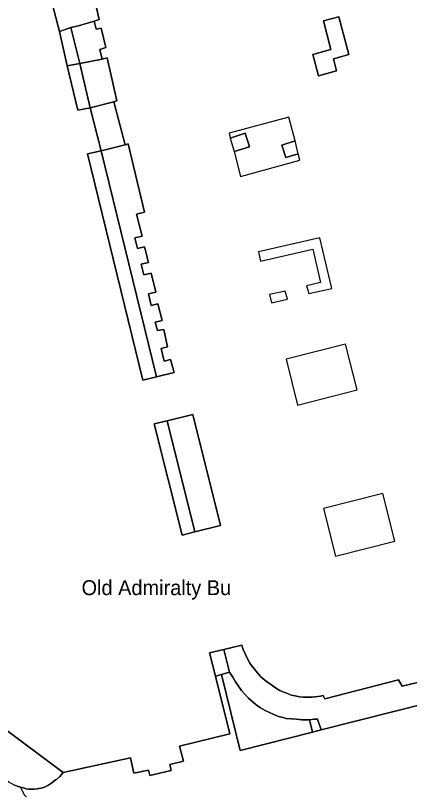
# Model space of a CAD drawing. Extents: x 529240 to 530363, y 179600 to 180767.
# Drawn here: x 529918.6 to 529964.9, y 180142.8 to 180233.6 of the extents above; entities that cross this region are included whole.
import ezdxf

# ---------------------------------------------------------------- set-up
doc = ezdxf.new("R2010")
doc.units = 0
for name, color, linetype in [('Building', 7, 'Continuous'), ('General surface', 7, 'Continuous'), ('Roadside', 7, 'Continuous'), ('Unclassified', 7, 'Continuous')]:
    doc.layers.add(name, color=color, linetype=linetype)

msp = doc.modelspace()

# ---------------------------------------------------------------- linework, layer by layer
at = {"layer": 'Building'}
for points in [[(529935.45, 180242.8), (529934.3, 180242.55), (529934.4, 180242.05), (529933.3, 180241.75), (529933.5, 180241.05), (529931.55, 180240.6), (529931.4, 180241.25), (529930, 180240.9), (529930.15, 180240.2), (529928.15, 180239.7), (529928.05, 180240.35), (529926.8, 180240.05), (529926.95, 180239.4), (529926.3, 180239.25), (529926.6, 180238.1), (529927.25, 180238.25), (529927.65, 180236.45), (529927, 180236.35), (529927.25, 180235.2), (529927.95, 180235.35), (529928.45, 180233.1), (529927.9, 180232.9)], [(529927.95, 180235.35), (529928.45, 180233.1), (529927.9, 180232.9), (529928.1, 180231.95), (529928.7, 180232.1), (529929.25, 180229.8), (529928.55, 180229.6), (529928.8, 180228.45), (529929.4, 180228.6), (529930.55, 180223.55), (529930.2, 180223.45), (529931.5, 180218.4), (529931.85, 180218.5), (529933.8, 180210.5), (529932.85, 180210.25), (529933.5, 180207.7), (529932.65, 180207.5), (529932.95, 180206.25), (529933.8, 180206.45), (529934.25, 180204.6), (529933.4, 180204.4), (529933.7, 180203.15), (529934.55, 180203.35), (529935.1, 180201.1), (529934.25, 180200.9), (529934.55, 180199.55), (529935.35, 180199.75), (529935.85, 180197.8), (529935.05, 180197.6), (529935.3, 180196.6), (529936.05, 180196.75), (529936.5, 180194.7), (529935.75, 180194.5), (529936.1, 180193), (529936.85, 180193.2), (529937.25, 180191.7), (529935.2, 180191.2), (529933.6, 180190.8), (529927.1, 180217.35), (529928.7, 180217.7), (529927.4, 180222.75), (529925.95, 180222.45), (529924.7, 180227.65), (529923.8, 180231.7), (529922.15, 180238.15)], [(529923.8, 180231.7), (529922.15, 180238.15)], [(529927.9, 180232.9), (529926.05, 180232.35)], [(529928.8, 180228.45), (529928.55, 180229.6), (529929.25, 180229.8), (529928.7, 180232.1), (529928.1, 180231.95), (529927.9, 180232.9)], [(529954.2, 180226.5), (529953.55, 180229), (529955.65, 180229.6), (529954.8, 180232.95), (529956.6, 180233.4), (529957.75, 180229), (529955.95, 180228.5), (529956.3, 180227.1), (529954.2, 180226.5)], [(529925.15, 180232.15), (529923.8, 180231.7)], [(529926.05, 180232.35), (529925.15, 180232.15)], [(529925.15, 180232.15), (529926.2, 180227.95)], [(529923.8, 180231.7), (529924.7, 180227.65)], [(529926.2, 180227.95), (529928.8, 180228.45)], [(529930.2, 180223.45), (529930.55, 180223.55), (529929.4, 180228.6), (529928.8, 180228.45)], [(529924.7, 180227.65), (529926.2, 180227.95)], [(529924.7, 180227.65), (529925.95, 180222.45), (529927.4, 180222.75)], [(529927.4, 180222.75), (529930.2, 180223.45)], [(529927.4, 180222.75), (529928.7, 180217.7)], [(529930.2, 180223.45), (529931.5, 180218.4)], [(529951.45, 180218.85), (529950.7, 180221.65), (529943.7, 180219.75)], [(529943.7, 180219.75), (529943.85, 180219.2)], [(529943.85, 180219.2), (529944.3, 180217.6)], [(529928.7, 180217.7), (529931.5, 180218.4)], [(529931.5, 180218.4), (529931.85, 180218.5), (529933.8, 180210.5), (529932.85, 180210.25), (529933.5, 180207.7), (529932.65, 180207.5), (529932.95, 180206.25), (529933.8, 180206.45), (529934.25, 180204.6), (529933.4, 180204.4), (529933.7, 180203.15), (529934.55, 180203.35), (529935.1, 180201.1), (529934.25, 180200.9), (529934.55, 180199.55), (529935.35, 180199.75), (529935.85, 180197.8), (529935.05, 180197.6), (529935.3, 180196.6), (529936.05, 180196.75), (529936.5, 180194.7), (529935.75, 180194.5), (529936.1, 180193), (529936.85, 180193.2), (529937.25, 180191.7), (529935.2, 180191.2)], [(529951.8, 180217.35), (529951.45, 180218.85)], [(529888.1, 180217.5), (529902.05, 180161.3), (529924.25, 180144.75)], [(529935.2, 180191.2), (529933.6, 180190.8), (529927.1, 180217.35), (529928.7, 180217.7)], [(529944.3, 180217.6), (529945.05, 180214.7), (529952, 180216.6), (529951.8, 180217.35)], [(529955.75, 180201.55), (529954.35, 180207.5), (529947.15, 180205.85), (529947.4, 180204.75), (529953.55, 180206.15), (529954.45, 180202.25), (529952.8, 180201.85), (529953.05, 180200.95), (529955.75, 180201.55)], [(529950.55, 180200.3), (529950.3, 180201.25), (529948.45, 180200.85), (529948.7, 180199.85), (529950.55, 180200.3)], [(529958.75, 180189.65), (529957.35, 180195), (529950.4, 180193.25), (529951.75, 180187.85), (529958.75, 180189.65)], [(529936.45, 180186), (529939.45, 180186.75), (529942.7, 180173.75), (529939.7, 180173)], [(529939.7, 180173), (529938.2, 180172.6), (529934.9, 180185.65), (529936.45, 180186)], [(529963.15, 180171.9), (529961.75, 180177.5), (529954.8, 180175.75), (529956.2, 180170.15), (529963.15, 180171.9)], [(529902.05, 180161.3), (529924.25, 180144.75), (529932.15, 180146.5), (529932.55, 180144.7), (529934.25, 180145.05), (529934.4, 180144.4), (529936.9, 180145), (529936.75, 180145.7), (529938.35, 180146.1), (529937.9, 180147.85), (529943.8, 180149.3), (529942.1, 180156.05), (529941.4, 180158.8), (529943.1, 180159.2), (529945.2, 180159.7), (529945.35, 180159.2), (529945.85, 180158.1), (529946.15, 180157.6), (529946.35, 180157.3), (529946.7, 180156.9), (529947.05, 180156.45), (529947.45, 180156), (529947.9, 180155.6), (529948.2, 180155.35), (529948.7, 180155.05), (529949.15, 180154.7), (529949.65, 180154.4), (529950.2, 180154.15), (529950.5, 180154.05), (529951, 180153.85), (529951.45, 180153.75), (529951.95, 180153.65), (529952.45, 180153.6), (529953.45, 180153.6), (529954.45, 180153.7), (529954.75, 180153.8), (529954.95, 180153.4), (529963.6, 180155.65), (529964, 180154.9), (529966.8, 180155.55)], [(529942.1, 180156.05), (529941.4, 180158.8), (529943.1, 180159.2)], [(529943.1, 180159.2), (529945.2, 180159.7), (529945.35, 180159.2), (529945.85, 180158.1), (529946.15, 180157.6), (529946.35, 180157.3), (529946.7, 180156.9), (529947.05, 180156.45), (529947.45, 180156), (529947.9, 180155.6), (529948.2, 180155.35), (529948.7, 180155.05), (529949.15, 180154.7), (529949.65, 180154.4), (529950.2, 180154.15), (529950.5, 180154.05), (529951, 180153.85), (529951.45, 180153.75), (529951.95, 180153.65), (529952.45, 180153.6), (529953.45, 180153.6), (529954.45, 180153.7), (529954.75, 180153.8), (529954.95, 180153.4), (529963.6, 180155.65), (529964, 180154.9), (529966.8, 180155.55)], [(529924.25, 180144.75), (529932.15, 180146.5), (529932.55, 180144.7), (529934.25, 180145.05), (529934.4, 180144.4), (529936.9, 180145), (529936.75, 180145.7), (529938.35, 180146.1), (529937.9, 180147.85), (529943.8, 180149.3), (529942.1, 180156.05)]]:
    msp.add_lwpolyline(points, dxfattribs=at)
for points in [[(529926.2, 180227.95), (529928.8, 180228.45), (529928.55, 180229.6), (529929.25, 180229.8), (529928.7, 180232.1), (529928.1, 180231.95), (529927.9, 180232.9), (529926.05, 180232.35), (529925.15, 180232.15)], [(529954.2, 180226.5), (529956.3, 180227.1), (529955.95, 180228.5), (529957.75, 180229), (529956.6, 180233.4), (529954.8, 180232.95), (529955.65, 180229.6), (529953.55, 180229)], [(529925.15, 180232.15), (529923.8, 180231.7), (529924.7, 180227.65), (529926.2, 180227.95)], [(529927.4, 180222.75), (529928.7, 180217.7), (529931.5, 180218.4), (529930.2, 180223.45)], [(529951.8, 180217.35), (529951.45, 180218.85), (529950.7, 180221.65), (529943.7, 180219.75), (529943.85, 180219.2), (529944.3, 180217.6), (529945.05, 180214.7), (529952, 180216.6)], [(529944.3, 180217.6), (529946.1, 180218.15), (529945.6, 180219.75), (529943.85, 180219.2)], [(529951.45, 180218.85), (529949.9, 180218.35), (529950.35, 180216.9), (529951.8, 180217.35)], [(529953.05, 180200.95), (529955.75, 180201.55), (529954.35, 180207.5), (529947.15, 180205.85), (529947.4, 180204.75), (529953.55, 180206.15), (529954.45, 180202.25), (529952.8, 180201.85)], [(529948.7, 180199.85), (529950.55, 180200.3), (529950.3, 180201.25), (529948.45, 180200.85)], [(529951.75, 180187.85), (529958.75, 180189.65), (529957.35, 180195), (529950.4, 180193.25)], [(529938.2, 180172.6), (529939.7, 180173), (529942.7, 180173.75), (529939.45, 180186.75), (529936.45, 180186), (529934.9, 180185.65)], [(529956.2, 180170.15), (529963.15, 180171.9), (529961.75, 180177.5), (529954.8, 180175.75)]]:
    msp.add_lwpolyline(points, close=True, dxfattribs=at)
at = {"layer": 'General surface'}
for points in [[(529922.15, 180238.15), (529923.8, 180231.7), (529925.15, 180232.15), (529926.05, 180232.35), (529927.9, 180232.9), (529928.45, 180233.1), (529927.95, 180235.35)], [(529918.45, 180143.3), (529918.85, 180143.15), (529919.25, 180143.03), (529919.6, 180142.95), (529919.9, 180142.85), (529920.2, 180142.8), (529920.85, 180142.8), (529921.2, 180142.85), (529921.8, 180142.95), (529922.05, 180143.05), (529922.45, 180143.25), (529922.9, 180143.55), (529923.35, 180143.9), (529923.45, 180143.95), (529923.85, 180144.3), (529924.25, 180144.75), (529902.05, 180161.3)], [(529966.8, 180155.55), (529964, 180154.9), (529963.6, 180155.65), (529954.95, 180153.4), (529954.75, 180153.8), (529954.45, 180153.7), (529953.45, 180153.6), (529952.45, 180153.6), (529951.95, 180153.65), (529951.45, 180153.75), (529951, 180153.85), (529950.5, 180154.05), (529950.2, 180154.15), (529949.65, 180154.4), (529949.15, 180154.7), (529948.7, 180155.05), (529948.2, 180155.35), (529947.9, 180155.6), (529947.45, 180156), (529947.05, 180156.45), (529946.7, 180156.9), (529946.35, 180157.3), (529946.15, 180157.6), (529945.85, 180158.1), (529945.35, 180159.2), (529945.2, 180159.7), (529943.1, 180159.2), (529943.75, 180156.55), (529944.15, 180155.95), (529944.45, 180155.4), (529945.15, 180154.4), (529945.55, 180153.95), (529946, 180153.5), (529946.9, 180152.7), (529947.4, 180152.35), (529947.95, 180152.05), (529948.95, 180151.55), (529949.5, 180151.35), (529950.05, 180151.2), (529950.4, 180151.1), (529951.05, 180151.05), (529951.6, 180151), (529952.25, 180150.95), (529953.15, 180150.95), (529953.65, 180151), (529954.1, 180151), (529954.5, 180149.75), (529980.1, 180156.2)], [(529980.1, 180156.2), (529954.5, 180149.75), (529953.5, 180149.5), (529945, 180147.35), (529942.8, 180156.25), (529942.1, 180156.05), (529943.8, 180149.3), (529937.9, 180147.85), (529938.35, 180146.1), (529936.75, 180145.7), (529936.9, 180145), (529934.4, 180144.4), (529934.25, 180145.05), (529932.55, 180144.7), (529932.15, 180146.5), (529924.25, 180144.75), (529923.85, 180144.3), (529923.45, 180143.95), (529923.35, 180143.9), (529922.9, 180143.55), (529922.45, 180143.25), (529922.05, 180143.05), (529921.8, 180142.95), (529921.2, 180142.85), (529920.85, 180142.8), (529920.2, 180142.8), (529919.9, 180142.85), (529919.6, 180142.95), (529919.25, 180143.03), (529919.7, 180142.1)]]:
    msp.add_lwpolyline(points, dxfattribs=at)
for points in [[(529954.2, 180226.5), (529956.3, 180227.1), (529955.95, 180228.5), (529957.75, 180229), (529956.6, 180233.4), (529954.8, 180232.95), (529955.65, 180229.6), (529953.55, 180229)], [(529930.2, 180223.45), (529930.55, 180223.55), (529929.4, 180228.6), (529928.8, 180228.45), (529926.2, 180227.95), (529927.4, 180222.75)], [(529927.4, 180222.75), (529926.2, 180227.95), (529924.7, 180227.65), (529925.95, 180222.45)], [(529943.85, 180219.2), (529945.6, 180219.75), (529946.1, 180218.15), (529944.3, 180217.6), (529945.05, 180214.7), (529952, 180216.6), (529951.8, 180217.35), (529950.35, 180216.9), (529949.9, 180218.35), (529951.45, 180218.85), (529950.7, 180221.65), (529943.7, 180219.75)], [(529931.5, 180218.4), (529928.7, 180217.7), (529935.2, 180191.2), (529937.25, 180191.7), (529936.85, 180193.2), (529936.1, 180193), (529935.75, 180194.5), (529936.5, 180194.7), (529936.05, 180196.75), (529935.3, 180196.6), (529935.05, 180197.6), (529935.85, 180197.8), (529935.35, 180199.75), (529934.55, 180199.55), (529934.25, 180200.9), (529935.1, 180201.1), (529934.55, 180203.35), (529933.7, 180203.15), (529933.4, 180204.4), (529934.25, 180204.6), (529933.8, 180206.45), (529932.95, 180206.25), (529932.65, 180207.5), (529933.5, 180207.7), (529932.85, 180210.25), (529933.8, 180210.5), (529931.85, 180218.5)], [(529935.2, 180191.2), (529928.7, 180217.7), (529927.1, 180217.35), (529933.6, 180190.8)], [(529955.75, 180201.55), (529954.35, 180207.5), (529947.15, 180205.85), (529947.4, 180204.75), (529953.55, 180206.15), (529954.45, 180202.25), (529952.8, 180201.85), (529953.05, 180200.95)], [(529950.55, 180200.3), (529950.3, 180201.25), (529948.45, 180200.85), (529948.7, 180199.85)], [(529958.75, 180189.65), (529957.35, 180195), (529950.4, 180193.25), (529951.75, 180187.85)], [(529936.45, 180186), (529939.7, 180173), (529942.7, 180173.75), (529939.45, 180186.75)], [(529939.7, 180173), (529936.45, 180186), (529934.9, 180185.65), (529938.2, 180172.6)], [(529963.15, 180171.9), (529961.75, 180177.5), (529954.8, 180175.75), (529956.2, 180170.15)], [(529942.8, 180156.25), (529943.75, 180156.55), (529943.1, 180159.2), (529941.4, 180158.8), (529942.1, 180156.05)], [(529953.15, 180150.95), (529952.25, 180150.95), (529951.6, 180151), (529951.05, 180151.05), (529950.4, 180151.1), (529950.05, 180151.2), (529949.5, 180151.35), (529948.95, 180151.55), (529947.95, 180152.05), (529947.4, 180152.35), (529946.9, 180152.7), (529946, 180153.5), (529945.55, 180153.95), (529945.15, 180154.4), (529944.45, 180155.4), (529944.15, 180155.95), (529943.75, 180156.55), (529942.8, 180156.25), (529945, 180147.35), (529953.5, 180149.5)], [(529953.5, 180149.5), (529954.5, 180149.75), (529954.1, 180151), (529953.65, 180151), (529953.15, 180150.95)]]:
    msp.add_lwpolyline(points, close=True, dxfattribs=at)
at = {"layer": 'Roadside'}
msp.add_lwpolyline([(529919.7, 180142.1), (529919.25, 180143.03), (529918.85, 180143.15), (529918.45, 180143.3)], dxfattribs=at)
at = {"layer": 'Unclassified'}
for points in [[(529926.2, 180227.95), (529927.4, 180222.75)], [(529943.85, 180219.2), (529945.6, 180219.75), (529946.1, 180218.15), (529944.3, 180217.6)], [(529951.45, 180218.85), (529949.9, 180218.35), (529950.35, 180216.9), (529951.8, 180217.35)], [(529928.7, 180217.7), (529935.2, 180191.2)], [(529936.45, 180186), (529939.7, 180173)], [(529943.75, 180156.55), (529943.1, 180159.2)], [(529919.25, 180143.03), (529918.85, 180143.15), (529918.45, 180143.3), (529918.1, 180143.5), (529917.9, 180143.6), (529903.3, 180155.55), (529902.4, 180156.45), (529902.05, 180156.85), (529901.7, 180157.3), (529901.25, 180158.05)], [(529942.8, 180156.25), (529943.75, 180156.55)], [(529943.75, 180156.55), (529944.15, 180155.95), (529944.45, 180155.4), (529945.15, 180154.4), (529945.55, 180153.95), (529946, 180153.5), (529946.9, 180152.7), (529947.4, 180152.35), (529947.95, 180152.05), (529948.95, 180151.55), (529949.5, 180151.35), (529950.05, 180151.2), (529950.4, 180151.1), (529951.05, 180151.05), (529951.6, 180151), (529952.25, 180150.95), (529953.15, 180150.95)], [(529942.1, 180156.05), (529942.8, 180156.25)], [(529942.8, 180156.25), (529945, 180147.35), (529953.5, 180149.5)], [(529954.5, 180149.75), (529980.1, 180156.2)], [(529953.15, 180150.95), (529953.65, 180151), (529954.1, 180151), (529954.5, 180149.75)], [(529953.15, 180150.95), (529953.5, 180149.5)], [(529953.5, 180149.5), (529954.5, 180149.75)], [(529924.25, 180144.75), (529923.85, 180144.3), (529923.45, 180143.95), (529923.35, 180143.9), (529922.9, 180143.55), (529922.45, 180143.25), (529922.05, 180143.05), (529921.8, 180142.95), (529921.2, 180142.85), (529920.85, 180142.8), (529920.2, 180142.8), (529919.9, 180142.85), (529919.6, 180142.95), (529919.25, 180143.03)], [(529919.25, 180143.03), (529919.7, 180142.1), (529920.9, 180141), (529921.9, 180140), (529922.8, 180138.6), (529923.2, 180137.95), (529923.6, 180137.2), (529923.8, 180136.9), (529924.55, 180135.35), (529925.2, 180134.1), (529926.85, 180130.35), (529927.5, 180128.55), (529927.95, 180127.25), (529928.5, 180125.1), (529931.174, 180114)]]:
    msp.add_lwpolyline(points, dxfattribs=at)

# ---------------------------------------------------------------- texts
msp.add_text('Old Admiralty Bu', height=1.75, dxfattribs=at).set_placement((529926.4, 180165.57))

doc.saveas('drawing.dxf')
